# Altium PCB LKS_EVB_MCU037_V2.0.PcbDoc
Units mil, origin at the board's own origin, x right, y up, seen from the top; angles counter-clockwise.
Board outline 2625 x 1560 mil, 2 copper layers (Top Layer, Bottom Layer); 33 components, 42 nets, 144 pads, 31 vias.
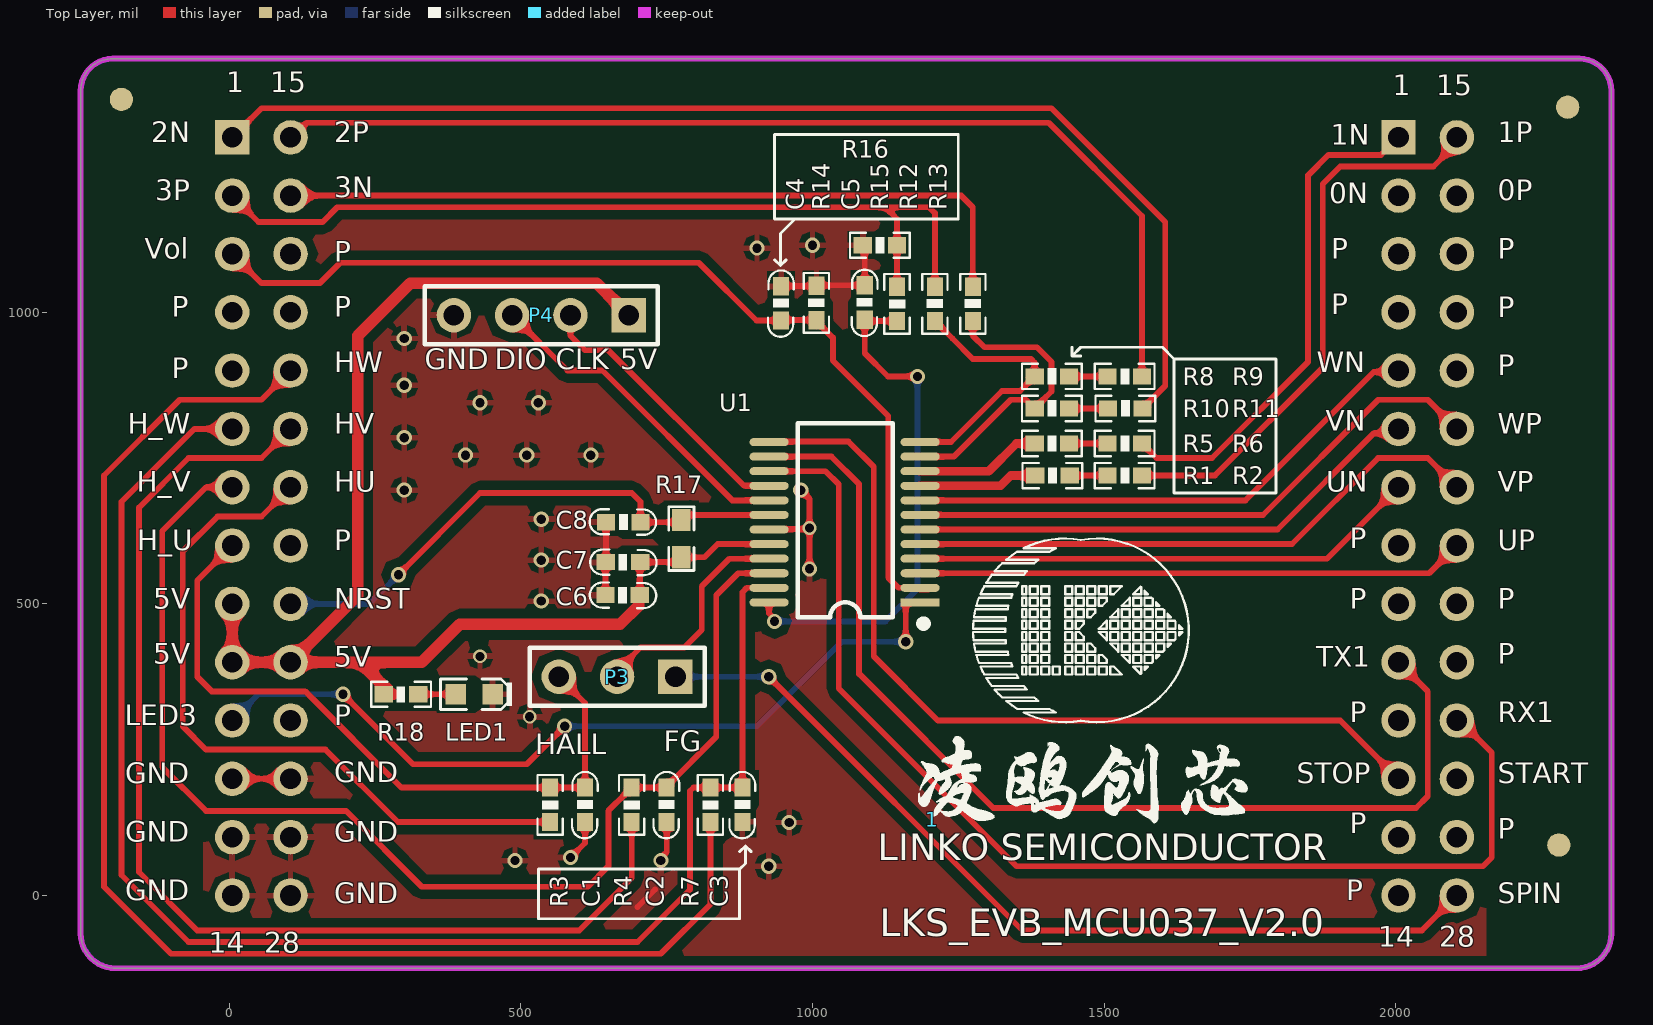
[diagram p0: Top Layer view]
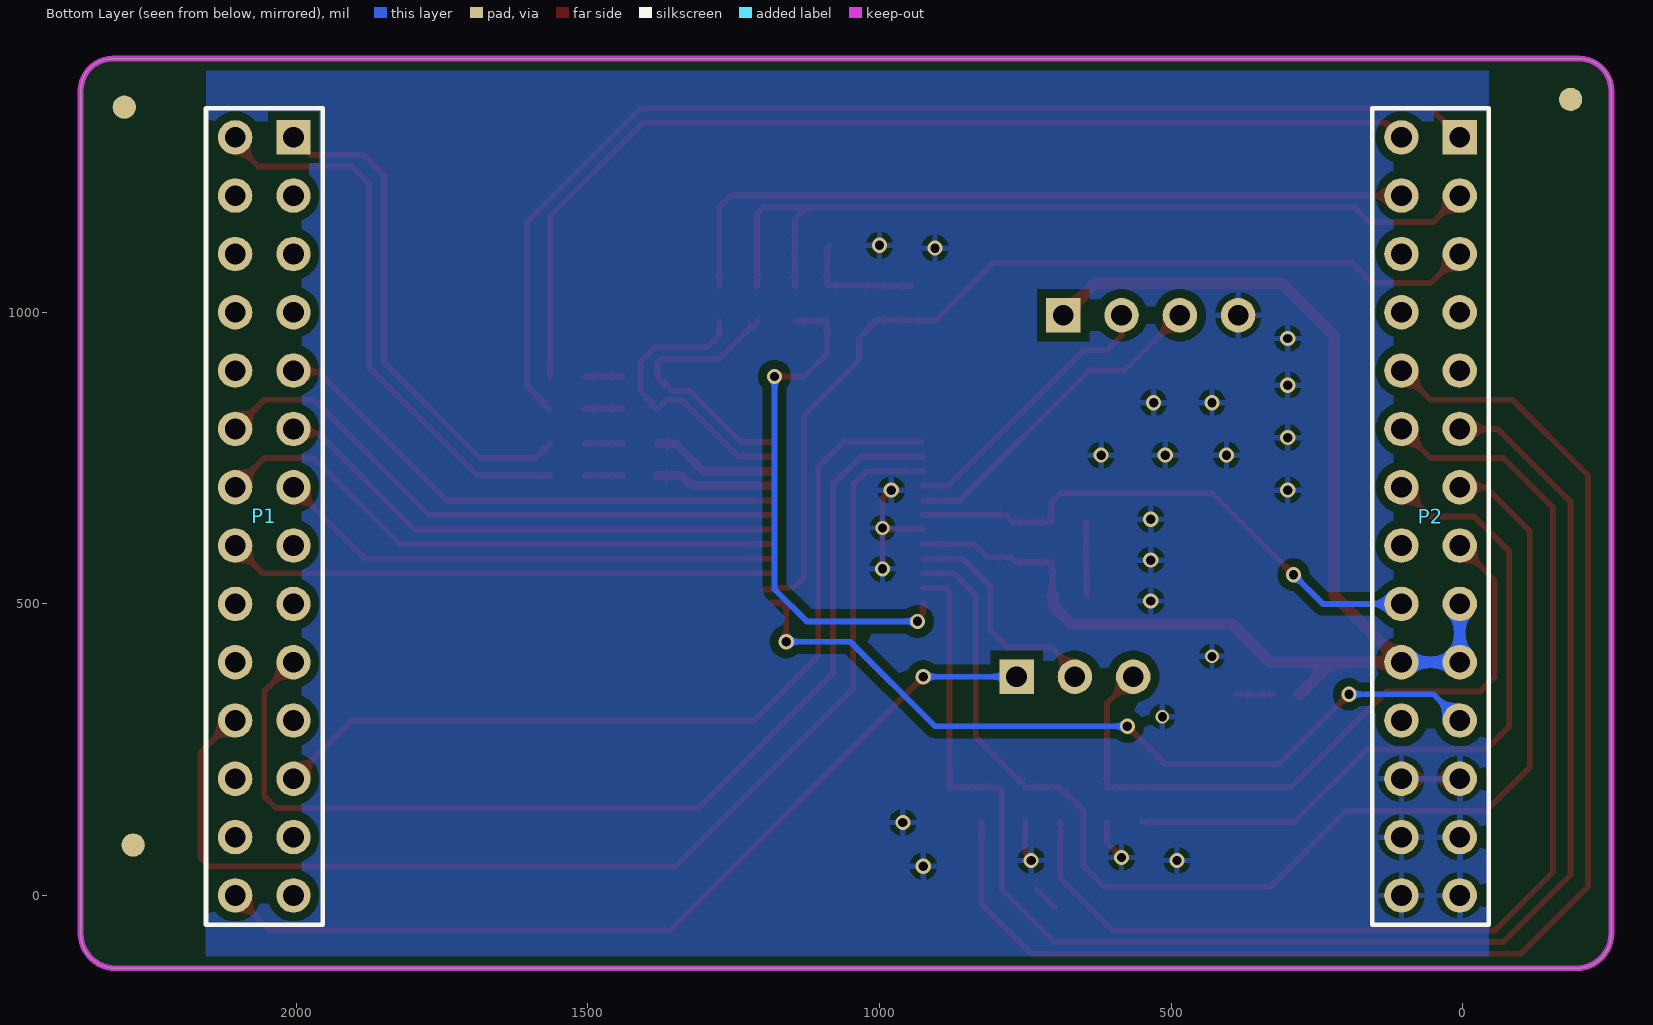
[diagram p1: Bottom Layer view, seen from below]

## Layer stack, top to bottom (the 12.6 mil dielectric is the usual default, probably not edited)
Top Solder: solder mask 0.4, Solder Resist, Dk 3.5
Top Layer: signal copper 1.4
Dielectric 1: dielectric 12.6, FR-4, Dk 4.8
Bottom Layer: signal copper 1.4
Bottom Solder: solder mask 0.4, Solder Resist, Dk 3.5

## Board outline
-255,-65 ccw(c-195,-65) -195,-125 2310,-125 ccw(c2310,-65) 2370,-65 2370,1380 ccw(c2315,1380) 2315,1435 -200,1435 ccw(c-200,1380) -255,1380

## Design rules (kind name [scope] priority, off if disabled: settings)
Clearance Clearance_1 [InPolygon] p1: gap=15 ignorepadtopadclearanceinfootprint=FALSE
Clearance [All] p2: gap=0.2 ignorepadtopadclearanceinfootprint=FALSE
ComponentClearance [All] p1: gap=0 collisioncheckmode=3 verticalgap=0 showdistances=FALSE
DiffPairsRouting DiffPair_DiffPairsRouting [All] p1: maxlimit=10 minlimit=10 mostfreqgap=10 toplayer_minwidth=15 toplayer_maxwidth=15 toplayer_prefwidth=15 bottomlayer_minwidth=15 bottomlayer_maxwidth=15 bottomlayer_prefwidth=15 maxuncoupledlength=500
DiffPairsRouting [All] p2: maxlimit=10 minlimit=10 mostfreqgap=10 toplayer_minwidth=15 toplayer_maxwidth=15 toplayer_prefwidth=15 bottomlayer_minwidth=15 bottomlayer_maxwidth=15 bottomlayer_prefwidth=15 maxuncoupledlength=500
MatchedLengths DiffPair_MatchedLengths [All] p1: tolerance=1000 checknetsindiffpair=TRUE checkdiffpairvsdiffpair=FALSE checkxsignals=FALSE checkothers=FALSE
PolygonConnect [All] p1: connectstyle=Relief reliefconductorwidth=10 reliefentries=4 polygonreliefangle="90 Angle" airgapwidth=10
RoutingVias [All] p1: holewidth=28 width=50 viastyle="Through Hole" minholewidth=28 minwidth=50 maxholewidth=28 maxwidth=50
SolderMaskExpansion [All] p1: expansion=4 istentingtop=FALSE
Width [All] p1: maxlimit=100 minlimit=10 preferedwidth=10
28 further rules are at their usual default settings.

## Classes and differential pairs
differential pair OPA2: +OPA2_P -OPA2_N

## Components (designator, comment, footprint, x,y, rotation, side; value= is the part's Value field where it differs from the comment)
1 "LKS_sign" LKS_LOGO2 1205,130 r0 top
C1 "10nF/16V" 0603C 610,185 r270 top
C2 "10nF/16V" 0603C 750,185 r270 top
C3 "10nF/16V" 0603C 880,185 r270 top
C4 "100nF/50V" 0603C 946.18,1044.92 r270 top
C5 "1nF/50V" 0603C 1089.71,1046.35 r270 top
C6 "10uF/10V" 0603C 645,515 r0 top
C7 "100nF/50V" 0603C 645.55,571.57 r0 top
C8 "100nF/50V" 0603C 705,640 r180 top
LED1 "LED" 0603D 420,345 r0 top
P1 "Header 14X2A" HDR2X14_CEN 2005,1300 r270 bottom
P2 "Header 14X2A" HDR2X14_CEN 5,1300 r270 bottom
P3 "Header 3" HDR1X3 765,375 r180 top
P4 "Header 4" HDR1X4 685,995 r180 top
R1 "20K1%" 0603R#1 1440.94,720 r180 top value=K
R2 "20K1%" 0603R#1 1565,720 r180 top value=K
R3 "2K" 0603R#1 550,125.94 r90 top value=K
R4 "2K" 0603R#1 690,125.94 r90 top value=K
R5 "20K1%" 0603R#1 1440,775 r180 top value=K
R6 "20K1%" 0603R#1 1565,775 r180 top value=K
R7 "2K" 0603R#1 825,125.94 r90 top value=K
R8 "20K1%" 0603R#1 1440,890 r180 top value=K
R9 "20K1%" 0603R#1 1565,890 r180 top value=K
R10 "20K1%" 0603R#1 1440,835 r180 top value=K
R11 "20K1%" 0603R#1 1565.94,835 r180 top value=K
R12 "1K1%" 0603R#1 1210,1044.06 r270 top value=K
R13 "1K1%" 0603R#1 1275,1044.06 r270 top value=K
R14 "1K1%" 0603R#1 1006.81,1045.71 r270 top value=K
R15 "1K1%" 0603R#1 1145,985 r90 top value=K
R16 "10R" 0603R#1 1145,1115 r180 top value=K
R17 "20K" 0603R#2 775,612 r270 top value=K
R18 "330R" 0603R#1 265,345 r0 top value=330
U1 "LKS037" SSOP24 1055,640 r180 top

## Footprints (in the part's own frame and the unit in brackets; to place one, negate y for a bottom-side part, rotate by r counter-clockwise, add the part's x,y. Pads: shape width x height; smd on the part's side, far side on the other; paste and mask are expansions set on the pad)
0603C [mm]
  rect 0.8x0.7 smd: 1(0,0) 2(1.5,0)
  silkscreen extent -0.68,-0.57 2.21,0.55
0603D [mm]
  rect 0.9x0.9 smd: 1(-0.813,0) 2(0.813,0)
  silkscreen extent -1.47,-0.66 1.65,0.66
0603R#1 [mm]
  rect 0.8x0.7 smd: 1(0,0) 2(1.5,0)
  silkscreen extent -0.55,-0.55 2.05,0.55
0603R#2 [mm]
  rect 0.965x0.813 smd: 1(-0.813,0) 2(0.813,0)
  silkscreen extent -1.38,-0.55 1.38,0.55
HDR1X3 [mm] "Connector; Header; 3 Position"
  rect 1.5x1.5 hole 0.9: 1(0,0)
  round 1.5 hole 0.9: 2(2.54,0) 3(5.08,0)
  silkscreen extent -1.27,-1.27 6.35,1.27
HDR1X4 [mm] "Connector; Header; 4 Position"
  rect 1.5x1.5 hole 0.9: 1(0,0)
  round 1.5 hole 0.9: 2(2.54,0) 3(5.08,0) 4(7.62,0)
  silkscreen extent -1.27,-1.27 8.89,1.27
HDR2X14_CEN [mm] "Connector; Header; 14x2 Position"
  rect 1.5x1.5 hole 0.9: 1(0,0)
  round 1.5 hole 0.9: 2(2.54,0) 3(5.08,0) 4(7.62,0) 5(10.16,0) 6(12.7,0) 7(15.24,0) 8(17.78,0) 9(20.32,0) 10(22.86,0) 11(25.4,0) 12(27.94,0) 13(30.48,0) 14(33.02,0) 15(0,-2.54) 16(2.54,-2.54) 17(5.08,-2.54) 18(7.62,-2.54) 19(10.16,-2.54) 20(12.7,-2.54) 21(15.24,-2.54) 22(17.78,-2.54) 23(20.32,-2.54) 24(22.86,-2.54) 25(25.4,-2.54) 26(27.94,-2.54) 27(30.48,-2.54) 28(33.02,-2.54)
  silkscreen extent -1.27,-3.81 34.29,1.27
LKS_LOGO2 [mil] "标?"
  silkscreen extent 70,167 440,482
SSOP24 [mil] "8.3*7.8*1.6（蒜米工坊）"
  rect 66.93x13.78 smd: 1(-129.5,137.5)
  oval 66.93x13.78 smd: 2(-129.5,112.5) 3(-129.5,87.5) 4(-129.5,62.5) 5(-129.5,37.5) 6(-129.5,12.5) 7(-129.5,-12.5) 8(-129.5,-37.5) 9(-129.5,-62.5) 10(-129.5,-87.5) 11(-129.5,-112.5) 12(-129.5,-137.5) 13(129.5,-137.5) 14(129.5,-112.5) 15(129.5,-87.5) 16(129.5,-62.5) 17(129.5,-37.5) 18(129.5,-12.5) 19(129.5,12.5) 20(129.5,37.5) 21(129.5,62.5) 22(129.5,87.5) 23(129.5,112.5) 24(129.5,137.5)
  silkscreen extent -140,-170 80,179, body extent -151,-168 153,159, height 65

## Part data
C1 C2 C3: library part CAP, "Capacitor"
C4 C5 C6 C7 C8: library part C, "Capacitor"
LED1: "LED_Light"
P1 P2: "Header, 14-Pin, Dual row"
P3: "Header, 3-Pin"
P4: "Header, 4-Pin"
R1 R2 R3 R4 R5 R6 R7 R8 R9 R10 R11 R12 R13 R14 R15 R16 R17 R18: library part Res, "Resistor"
U1: library part LKS32MC037M6S8, "Chip"

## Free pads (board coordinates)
  round 40 all layers, no hole: 2(2295,1351.86) 3(2280,86.43) 4(-185,1365)

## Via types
v1: diameter 26, hole 16, Top Layer to Bottom Layer, 28 vias
v2: diameter 23.62, hole 15.75, Top Layer to Bottom Layer, 3 vias

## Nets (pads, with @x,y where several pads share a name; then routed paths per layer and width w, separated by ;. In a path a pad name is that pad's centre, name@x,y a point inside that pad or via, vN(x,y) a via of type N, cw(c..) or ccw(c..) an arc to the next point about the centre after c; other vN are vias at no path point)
+5V: C6.2 C7.2 P2.9 P2.10 P2.24 P4.1 R17.2 R18.1 U1.20 | length 2559
  Top Layer w10: C6.2 704.06,571.02 C7.2 766.57,571.57 R17.2 815,580 837.5,602.5 U1.20
  Top Layer w20: P2.9 P2.10 P2.24 ; 280.94,345 278.98,345 223.98,400 ; P4.1 630,1050 310,1050 220,960 220,515 P2.24 ; C6.2 701.94,512.88 701.94,496.94 670,465 395,465 330,400 223.98,400 ; P2.24 223.98,400
  Bottom Layer w20: P2.9 P2.10 P2.24
GND: C1.2 C2.2 C3.2 C4.1 C5.1 C6.1 C7.1 C8.2 LED1.2 P2.12 P2.13 P2.14 P2.26 P2.27 P2.28 P4.4 R14.1 R16.2 U1.19 | length 835.3
  Top Layer w10: P2.12 P2.26 ; v1(585,65) 610,90 C1.2 ; C6.1 645,571.02 C7.1 645.94,571.97 C8.2 ; 700,-20 730,10 ; v1(740,60) 740,64.33 750,74.33 C2.2 ; U1.19 926.22,628.22 993.22,628.22 v2(995,630) ; C4.1 1006.02,1044.92 R14.1 1007.45,1046.35 C5.1 1089.71,1111.24 R16.2 ; v1(980,695) 995,680 v2(995,630) ; v1(995,560) v2(995,630)
  other v1: 925,50 490,60 960,125 535,505 535,575 535,645 300,695 405,755 510,755 620,755 300,785 430,845 530,845 300,875 300,955 905,1110 1000,1115
  other v2: 515,306.54 430,410
GND0: P2.16 R13.1 | length 1314.2
  Top Layer w10: P2.16 1255,1200 1275,1180 R13.1
HALL_U: C1.1 P2.8 P3.3 R3.2 | length 1202.2
  Top Layer w10: P2.8 -55,540 -55,375 -30,350 130,350 295,185 R3.2 C1.1 610,330 P3.3
HALL_V: C2.1 P2.7 R4.2 U1.22 | length 2104.4
  Top Layer w10: P2.7 -40,700 -115,625 -115,220 -40,145 200,145 330,15 615,15 650,50 650,145 679.25,174.25 681.22,174.25 690,183.03 R4.2 C2.1 750,186.97 835,271.97 835,515 872.5,552.5 U1.22
HALL_W: C3.1 P2.6 R7.2 U1.23 | length 2586.9
  Top Layer w10: P2.6 -60,800 -185,675 -185,35 -70,-80 700,-80 790,10 790,179.14 795.86,185 R7.2 C3.1 880,520 887.5,527.5 U1.23
HU: P2.21 R3.1 | length 1228.5
  Top Layer w10: P2.21 55,650 -20,650 -80,590 -80,290 -40,250 165,250 289.06,125.94 R3.1
HV: P2.20 R4.1 | length 1960.6
  Top Layer w10: P2.20 55,750 -70,750 -155,665 -155,40 -55,-60 600,-60 690,30 R4.1
HW: P2.19 R7.1 | length 2363.3
  Top Layer w10: P2.19 55,850 -85,850 -215,720 -215,15 -100,-100 740,-100 825,-15 R7.1
LED3: P2.11 U1.1 | length 1401.2
  Top Layer w10: v1(195,345) 315,225 510,225 v1(575,290) ; v1(1160,435) 1160,500.61 1161.89,502.5 U1.1
  Bottom Layer w10: P2.11 50,345 v1(195,345) ; v1(575,290) 905,290 1050,435 v1(1160,435)
NetLED1_1: LED1.1 R18.2 | length 63
  Top Layer w10: R18.2@325,345 LED1.1
NetP3_2: P3.2 U1.21 | length 394.2
  Top Layer w10: P3.2 665,385 705,425 780,425 810,455 810,530 857.5,577.5 U1.21
NetR1_1: R1.1 R2.2 | length 65
  Top Layer w10: R1.1 R2.2
NetR5_1: R5.1 R6.2 | length 65.9
  Top Layer w10: R5.1 R6.2
NetR8_1: R8.1 R9.2 | length 65.9
  Top Layer w10: R8.1 R9.2
NetR10_1: R10.1 R11.2 | length 66.9
  Top Layer w10: R10.1 R11.2
NRST: C8.1 P2.23 R17.1 U1.18 | length 945.6
  Top Layer w10: v1(290,550) 430,690 690,690 705,675 C8.1 771,640 R17.1 783.5,652.5 U1.18
  Bottom Layer w10: P2.23 240,500 v1(290,550)
OC: C5.2 R15.1 U1.24 | length 889.8
  Top Layer w10: U1.24 925.5,483.83 935,474.33 v1(935,470) ; R15.1 1092,985 C5.2 1089.71,929.71 1129.42,890 v1(1180,890)
  Bottom Layer w10: v1(935,470) 1125,470 1180,525 v1(1180,890)
OPA2_N: R5.2 U1.10 | length 214.2
  Top Layer w15: U1.10 1302.5,727.5 1350,775 R5.2@1378.98,775
OPA2_P: R1.2 U1.9 | length 204.6
  Top Layer w15: U1.9 1322.5,702.5 1340,720 R1.2
OPA3_IN: R10.2 R13.2 U1.11 | length 516
  Top Layer w10: U1.11 1242.5,752.5 1340,850 1365.94,850 1370.2,845.75 1370.2,843.78 1378.98,835 1382.91,835 1391.69,843.78 1391.69,845.75 1410,864.06 1410,915 1385,940 1295,940 1275,960 R13.2
OPA3_IP: R8.2 R12.2 U1.12 | length 468.6
  Top Layer w10: U1.12 1237.5,777.5 1325,865 1355.94,865 R8.2 1380.94,914.06 1375,920 1275,920 1240,955 1220.75,974.25 1218.78,974.25 1210,983.03 R12.2
PGND: P2.2 R12.1 R15.2 R16.1 | length 1508.3
  Top Layer w10: P2.2 50,1155 160,1155 185,1180 1125,1180 ; R15.2 R16.1 1145,1160 1125,1180 ; R12.1 1210,1170 1200,1180 1125,1180
PGND0: P1.2
PGND1: P1.1 R6.1 | length 865.6
  Top Layer w10: R6.1 1590,750 1685,750 1850,915 1850,1235 1885,1270 1975,1270 P1.1
PGND2: P2.1 R11.1 | length 2038.8
  Top Layer w10: P2.1 55,1350 1410,1350 1605,1155 1605,874.06 1576.69,845.75 1576.69,843.78 1567.91,835 R11.1
RXD1: P1.25 U1.15 | length 1994.1
  Top Layer w10: U1.15 1022.5,727.5 1045,705 1045,355 1350,50 2150,50 2165,65 2165,245 2110,300 P1.25
SPIN: P1.28 P3.1 | length 1545
  Top Layer w10: v1(925,375) 1360,-60 2045,-60 P1.28
  Bottom Layer w10: P3.1 v1(925,375)
STOP1: P1.12 U1.13 | length 1507.1
  Top Layer w10: U1.13@927.81,778.22 1061.78,778.22 1105,735 1105,410 1215,300 1905,300 P1.12
SWCLK: P4.2 U1.16 | length 482.2
  Top Layer w10: P4.2 585,960 610,935 650,935 882.5,702.5 U1.16
SWDIO: P4.3 U1.17 | length 572
  Top Layer w10: P4.3 580,900 640,900 862.5,677.5 U1.17
TXD1: P1.10 U1.14 | length 1828.4
  Top Layer w10: U1.14 1032.5,752.5 1080,705 1080,380 1310,150 2035,150 2055,170 2055,350 P1.10
UN: P1.7 U1.4 | length 871.2
  Top Layer w10: U1.4 1882.5,577.5 P1.7
UP: P1.22 U1.3 | length 940.2
  Top Layer w10: U1.3 2057.5,552.5 P1.22
UP-: P2.15 R9.1 | length 1811.6
  Top Layer w10: P2.15 107.56,1300 132.56,1325 1405,1325 1565,1165 R9.1
VN: P1.6 U1.6 | length 892
  Top Layer w10: U1.6 1797.5,627.5 1962.6,792.6 1997.6,792.6 P1.6
VOL_ADC: C4.2 P2.3 R14.2 U1.2 | length 1647
  Top Layer w10: P2.3 55,1050 155,1050 190,1085 805,1085 904.13,985.87 C4.2 946.97,986.65 R14.2 1006.81,984.69 1035,956.5 1035,917.17 1130,822.17 1130,545 1147.5,527.5 U1.2 ; U1.2@1184.5,524.84 U1.2@1198.7,524.84
VP: P1.21 U1.5 | length 1002.3
  Top Layer w10: U1.5 1822.5,602.5 1970,750 2055,750 P1.21
VP-: P1.15 R2.1 | length 970.6
  Top Layer w10: R2.1 1690,720 1875,905 1875,1220 1905,1250 2065,1250 2105,1290 P1.15
WN: P1.5 U1.8 | length 912.7
  Top Layer w10: U1.8 1742.5,677.5 1962.6,897.6 2002.6,897.6 P1.5
WP: P1.20 U1.7 | length 1023
  Top Layer w10: U1.7 1772.5,652.5 1970,850 2055,850 P1.20
WP-: P1.16
pads on no net: P1.3 P1.4 P1.8 P1.9 P1.11 P1.13 P1.14 P1.17 P1.18 P1.19 P1.23 P1.24 P1.26 P1.27 P2.4 P2.5 P2.17 P2.18 P2.22 P2.25

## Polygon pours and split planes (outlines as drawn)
GND on Bottom Layer "GND_L02_P001" (solid, remove dead copper, pour order 1): -45,-125 2155,-125 2155,1435 -45,1435
GND on Top Layer "GND_L01_P004" (solid, remove dead copper, pour order 4): -45,-125 -45,1435 2155,1435 2155,-125

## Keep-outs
Keep-Out Layer:
  the board outline again, w10

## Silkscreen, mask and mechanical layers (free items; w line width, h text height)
Top Overlay:
  drawing of 35 lines, arcs and shapes, not listed
  text "2N" at -133.73,1280 h60
  text "2P" at 180,1280 h60
  text "1P" at 2175.06,1280 h60
  text "1N" at 1888.64,1275 h60
  text "3N" at 179.94,1185 h60
  text "3P" at -126.62,1180 h60
  text "0P" at 2175,1180 h60
  text "0N" at 1885.92,1175 h60
  text "Vol" at -144.61,1080 h60
  text "P" at 1889.42,1080 h60
  text "P" at 2175.06,1080 h60
  text "P" at 180,1075 h60
  text "P" at 1889.86,985 h60
  text "P" at -98.71,980 h60
  text "P" at 180,980 h60
  text "P" at 2175.06,979.33 h60
  text "GND" at 335,890 h60
  text "DIO" at 455,890 h60
  text "CLK" at 560,890 h60
  text "5V" at 670,890 h60
  text "HW" at 180,885 h60
  text "WN" at 1865,885 h60
  text "P" at 2175.06,880 h60
  text "P" at -98.71,875 h60
  text "VN" at 1880.26,785 h60
  text "H_W" at -173.97,780 h60
  text "HV" at 180,780 h60
  text "WP" at 2175.06,780 h60
  text "H_V" at -158.65,680 h60
  text "HU" at 180,680 h60
  text "UN" at 1880.65,680 h60
  text "VP" at 2175,680 h60
  text "P" at 1921.61,583.02 h60
  text "H_U" at -158.2,580 h60
  text "P" at 180,580 h60
  text "UP" at 2175,580 h60
  text "5V" at -130.4,480 h60
  text "NRST" at 180,480 h60
  text "P" at 1921.61,480 h60
  text "P" at 2175.06,480 h60
  text "5V" at -130.4,385 h60
  text "P" at 2175.06,385 h60
  text "5V" at 179.94,380 h60
  text "TX1" at 1864,380 h60
  text "P" at 1921.61,285 h60
  text "RX1" at 2175.06,285 h60
  text "LED3" at -178.91,280 h60
  text "P" at 180,280 h60
  text "FG" at 745,235 h60
  text "HALL" at 525,230 h60
  text "GND" at 180,181.7 h60
  text "GND" at -178.07,180 h60
  text "STOP" at 1830.76,180 h60
  text "START" at 2175,180 h60
  text "P" at 1921.61,95 h60
  text "P" at 2175.06,85 h60
  text "GND" at -178.07,80 h60
  text "GND" at 180,80 h60
  text "GND" at -178.07,-20 h60
  text "P" at 1915,-20 h60
  text "GND" at 180,-25 h60
  text "SPIN" at 2175,-25 h60
  text "LKS_EVB_MCU037_V2.0" at 1115,-85 h80
Top Solder:
  circle w78: c-185,1365 r17
  circle w78: c2280,86.43 r17
  circle w78: c2295,1351.86 r17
